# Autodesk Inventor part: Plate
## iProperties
Shininess: 64.0
Length Units: 11269
Angle Units: 11279
Time Units: 11290
Mass Units: 11283
Length Display Precision: 3
Angle Display Precision: 2
Compacted: True
Part Number: Plate
Document SubType Name: Modeling
Created: 2003-01
Designer: Owner
Density: 0.0
Volumn: 0.0
Area: 0.0
PropertySet Name: Model Information
Control State: 0
Master: False
Checked Out: False
Author: Owner
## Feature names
1. Extrusion1
